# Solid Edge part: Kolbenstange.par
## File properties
Username: ahadarics
Dokumentum tartalom típus: 0
Author: ahadarics
Last saved by: ahadarics
Revision: 83
Sűrűség: 0,000 kg/m^3
Pontosság: 0,990
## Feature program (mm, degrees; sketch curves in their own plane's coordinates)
base feature "unnamed BaseFeature 1"
thread "unnamed Thread 1"
sketch for "Kihúzás_1" plane through (59.75, 0, 0) normal (1, 0, 0) x-axis (0, -1, 0)
  circle centre (0, 0) radius 10
extrude "Kihúzás_1" add finite 32 along -normal
chamfer "Letörés_1" setback 0.4
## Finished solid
Body 1: solid body, 13 faces, 23 edges, 12 vertices.
  Faces by surface: plane 9, cylinder 3, cone 1
  Edges by curve: line 12, circle 11
Bounding box of the edges (mm): 293.500 x 20.000 x 20.000, from (-233.75, -10, -10) to (59.75, 10, 10).
Cylindrical faces by radius (mm): R4 x2, R10 x1
Conical faces (half-angle, radius in mm at the cone's reference point): 45 deg R3.6 x1
Planar faces by outward normal: +x 3, +z 1, -x 4, -z 1
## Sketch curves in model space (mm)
circle centre (59.75, 0, 0) radius 10
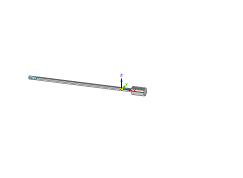
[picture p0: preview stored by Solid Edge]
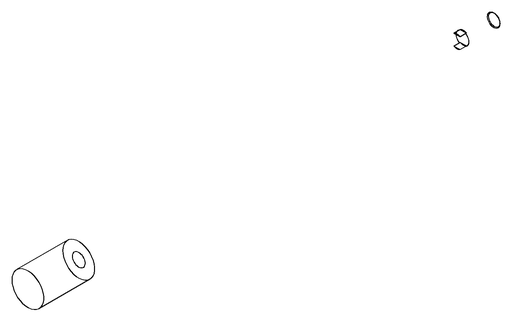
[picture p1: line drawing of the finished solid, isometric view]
